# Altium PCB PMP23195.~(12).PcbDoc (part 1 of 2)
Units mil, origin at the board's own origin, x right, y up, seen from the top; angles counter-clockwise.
Board outline 3600 x 3375 mil, 4 copper layers (Top Layer, Signal Layer 1, Signal Layer 2, Bottom Layer), stack 39.6 mil thick; 101 components, 57 nets, 256 pads, 67 vias.
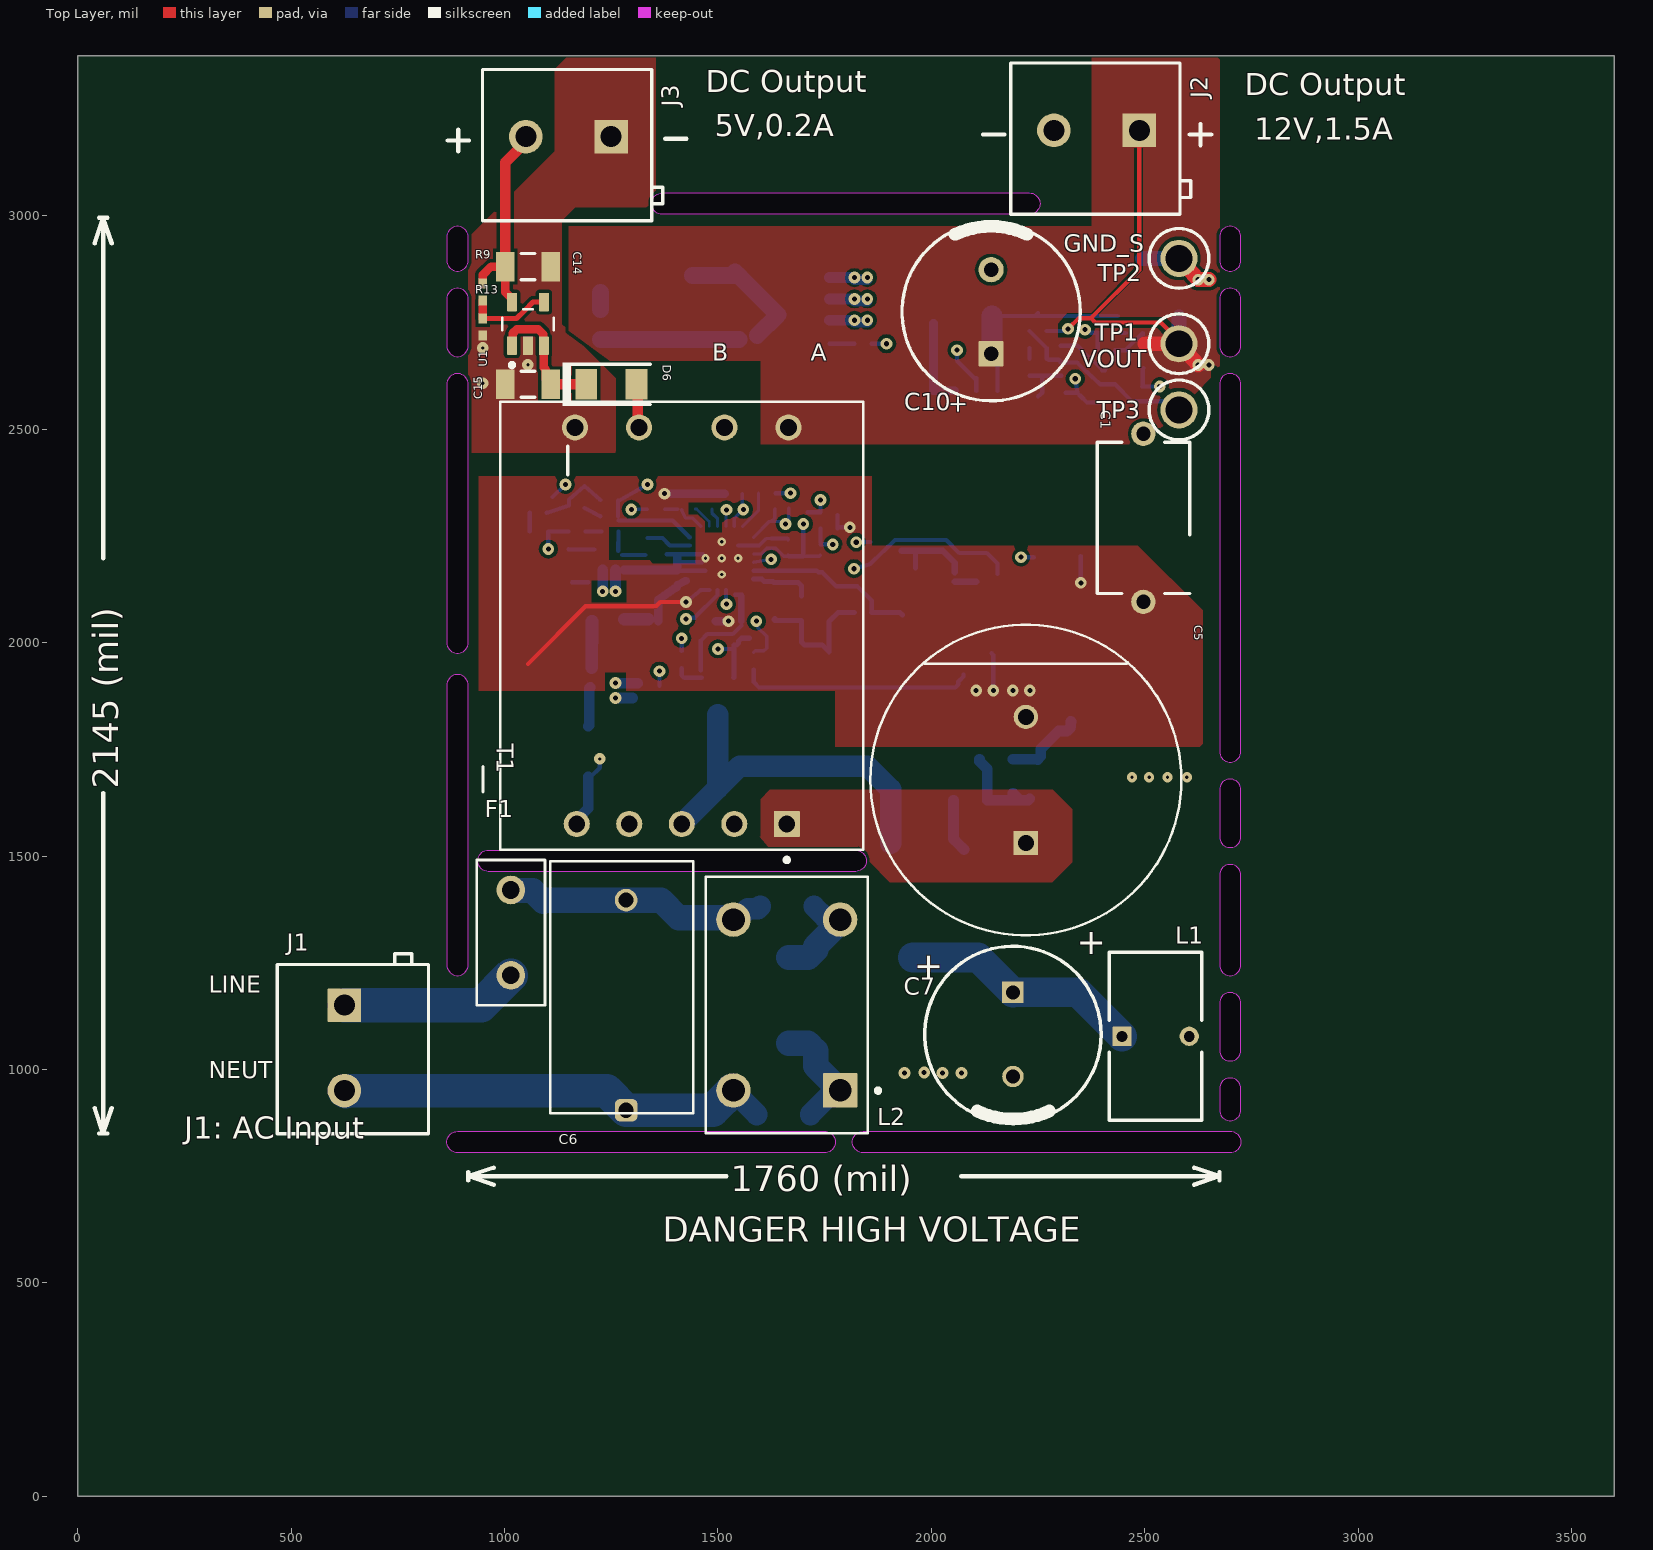
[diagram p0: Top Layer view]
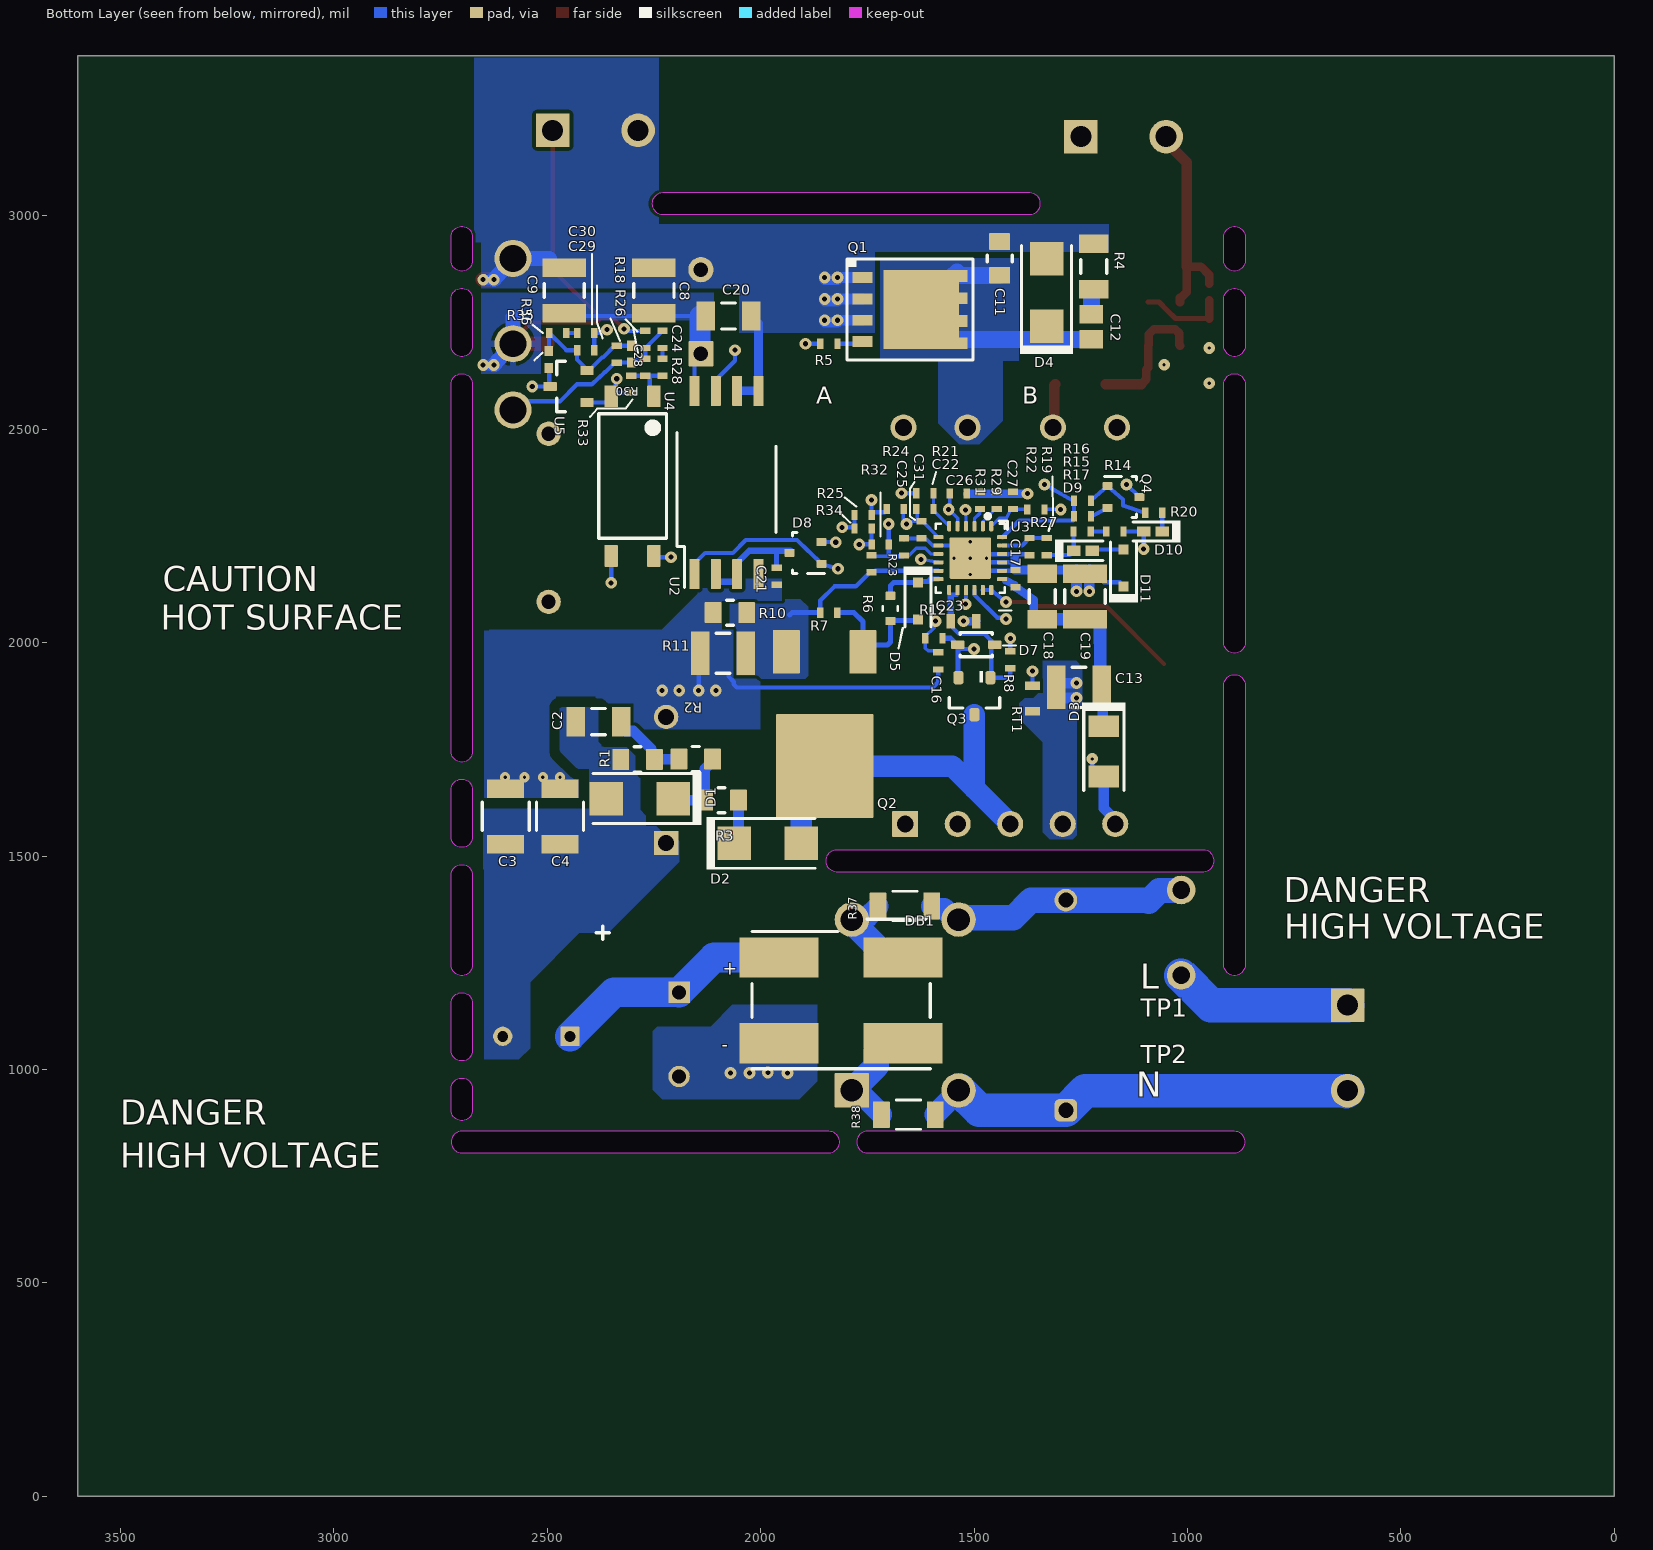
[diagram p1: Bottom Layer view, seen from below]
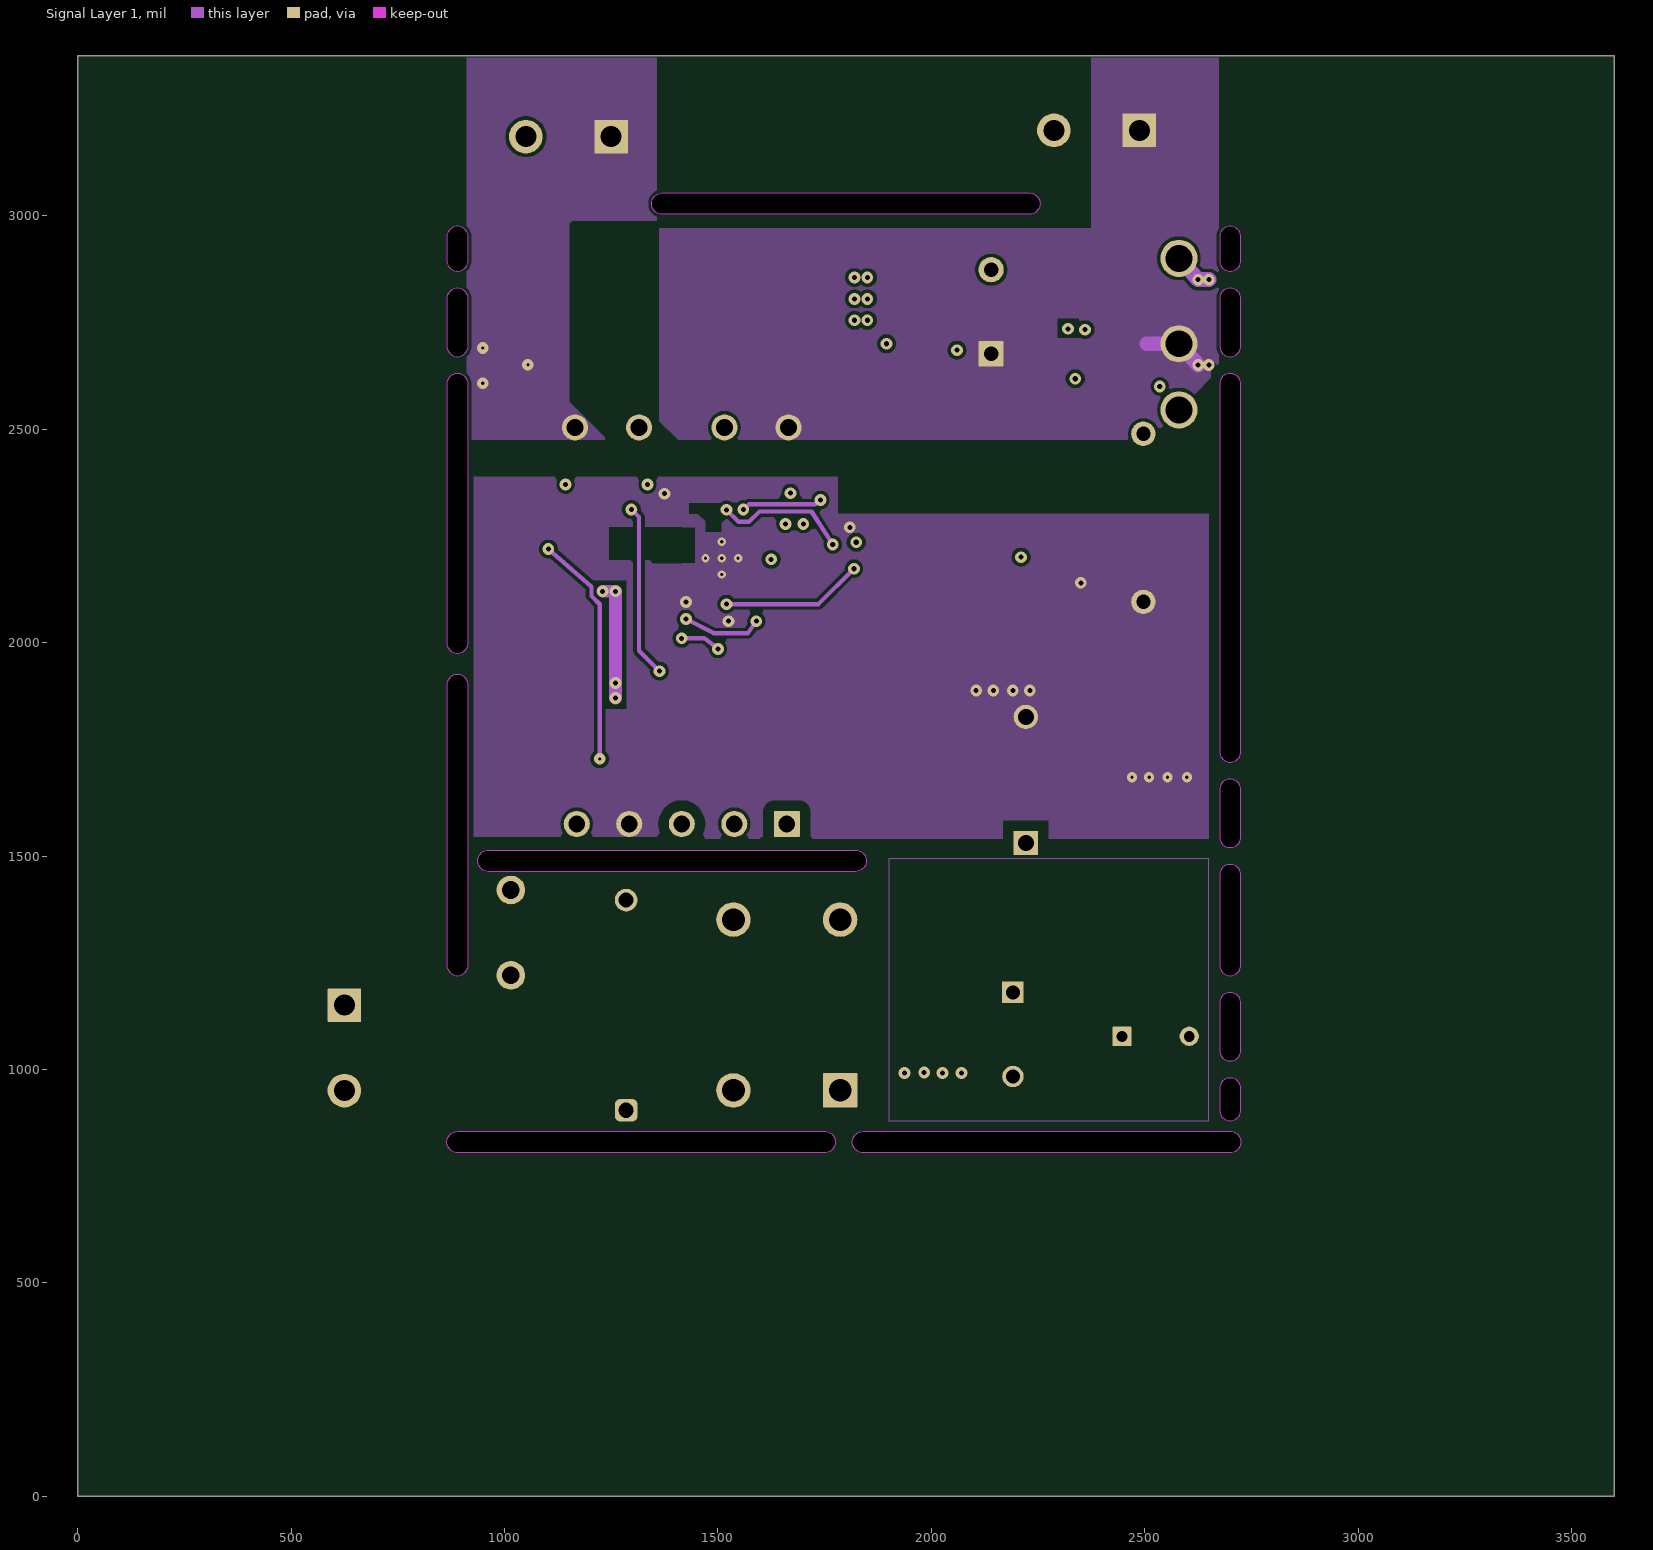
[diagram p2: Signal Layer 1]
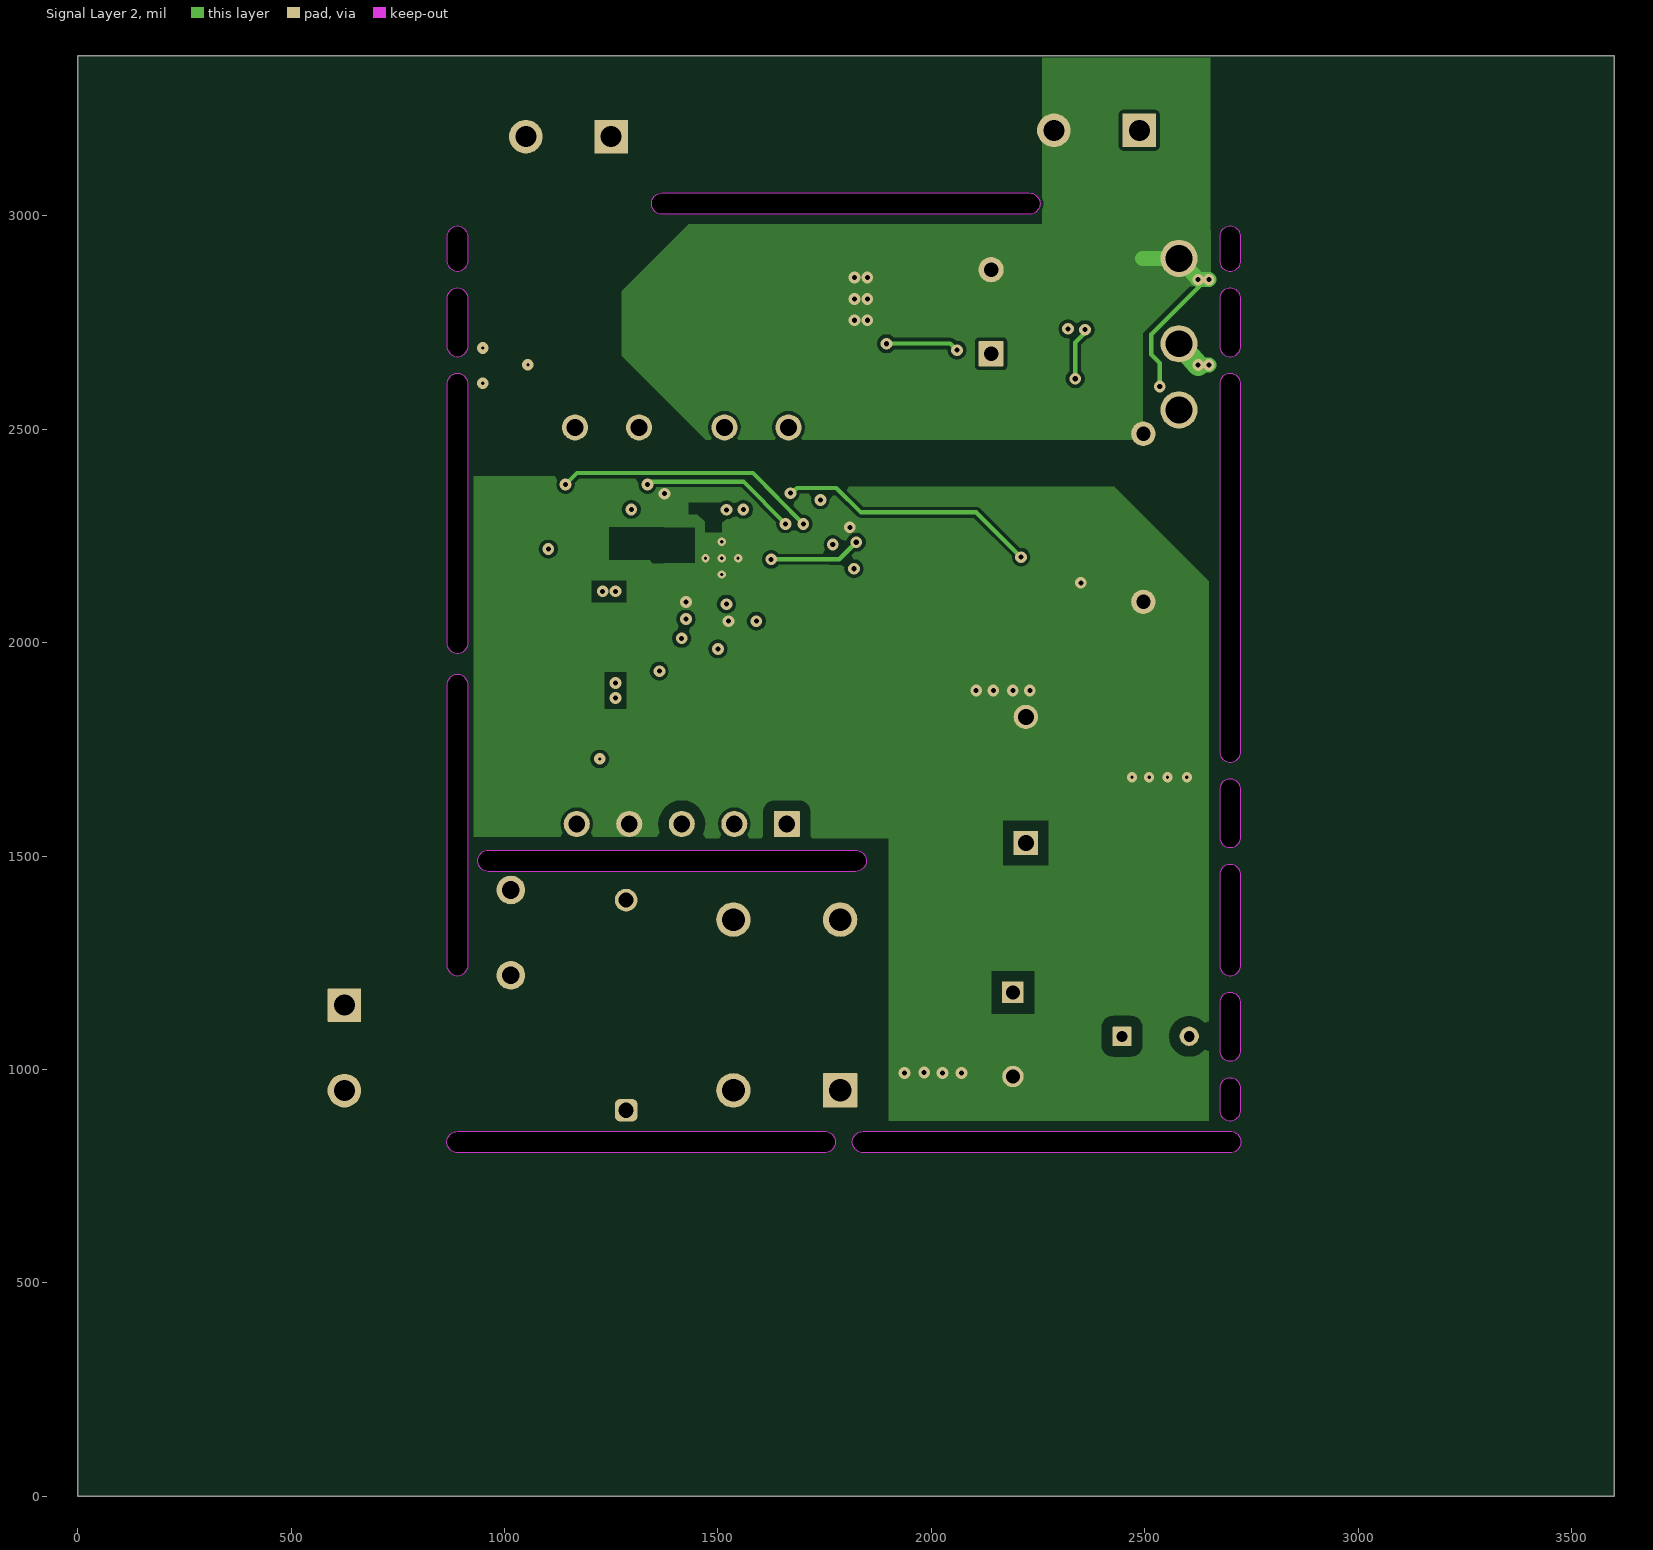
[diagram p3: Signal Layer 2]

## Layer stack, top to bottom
Top Solder: solder mask 0.4, Solder Resist, Dk 3.5
Top Layer: signal copper 1.4
Dielectric 1: prepreg 8, FR-4, Dk 4.2
Signal Layer 1: signal copper 1.4
Dielectric 2: core 18, FR-4, Dk 4.2
Signal Layer 2: signal copper 1.4
Dielectric 3: prepreg 8, FR-4, Dk 4.2
Bottom Layer: signal copper 1.4
Bottom Solder: solder mask 0.4, Solder Resist, Dk 3.5

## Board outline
0,0 3600,0 3600,3375 0,3375
cut-out: 962.45,1463.71 cw(c962.45,1488.72) 962.45,1513.74 1822.45,1513.74 cw(c1822.45,1488.72) 1847.47,1488.72 cw(c1822.45,1488.72) 1822.45,1463.71
cut-out: 1369.48,3003.15 cw(c1369.48,3028.16) 1369.48,3053.18 2229.48,3053.18 cw(c2229.48,3028.16) 2254.5,3028.16 cw(c2229.48,3028.16) 2229.48,3003.15
cut-out: 2674.99,2895 ccw(c2700,2895) 2725.01,2895 2725.01,2950 ccw(c2700,2950) 2674.99,2950
cut-out: 2674.99,2695 ccw(c2700,2695) 2725.01,2695 2725.01,2805 ccw(c2700,2805) 2674.99,2805
cut-out: 2674.99,1545 ccw(c2700,1545) 2725.01,1545 2725.01,1655 ccw(c2700,1655) 2674.99,1655
cut-out: 2674.99,1245 ccw(c2700,1245) 2725.01,1245 2725.01,1455 ccw(c2700,1455) 2674.99,1455
cut-out: 2674.99,1045 ccw(c2700,1045) 2725.01,1045 2725.01,1155 ccw(c2700,1155) 2674.99,1155
cut-out: 2674.99,905 ccw(c2700,905) 2725.01,905 2725.01,955 ccw(c2700,955) 2674.99,955
cut-out: 1840,804.99 cw(c1840,830) 1840,855.01 2700,855.01 cw(c2700,830) 2725.01,830 cw(c2700,830) 2700,804.99
cut-out: 890,804.99 cw(c890,830) 890,855.01 1750,855.01 cw(c1750,830) 1775.01,830 cw(c1750,830) 1750,804.99
cut-out: 864.98,1245 ccw(c890,1245) 915.02,1245 915.02,1900 ccw(c890,1900) 864.98,1900
cut-out: 864.98,2695 ccw(c890,2695) 915.02,2695 915.02,2805 ccw(c890,2805) 864.98,2805
cut-out: 864.98,2000 ccw(c890,2000) 915.02,2000 915.02,2605 ccw(c890,2605) 864.98,2605
cut-out: 864.98,2895 ccw(c890,2895) 915.02,2895 915.02,2950 ccw(c890,2950) 864.98,2950
cut-out: 2674.99,1745 ccw(c2700,1745) 2725.01,1745 2725.01,2605 ccw(c2700,2605) 2674.99,2605

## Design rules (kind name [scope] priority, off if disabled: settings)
AcuteAngle [All] p1: minimum=5.00000000000000E+0000 checktracksonly=FALSE
AssemblyTestPointUsage [All] p1: valid=2
BoardOutlineClearance BoardOutlineClearance_MountingHoles [OnCopper and InComponentClass('Mounting Holes')] p1: gap=15 ignorepadtopadclearanceinfootprint=FALSE
BoardOutlineClearance BoardOutlineClearance_Poly [OnCopper and InPoly] p2: gap=3.94 ignorepadtopadclearanceinfootprint=FALSE
BoardOutlineClearance [OnCopper and Not InComponentClass('Logo') and not InComponentClass('FiducialMark') and not InRegion(1000,500,4000,800)] p3: gap=4.53 ignorepadtopadclearanceinfootprint=FALSE
Clearance Clearance_HV [InNetClass('HV') vs not OnMultiLayer] p1: gap=25 ignorepadtopadclearanceinfootprint=TRUE // 1mm Clearance
Clearance Clearance_Keepouts [((IsTrack Or IsArc) And Not InPoly) And IsFree and IsKeepOut vs ((IsTrack Or IsArc) And Not InPoly) And IsFree and IsKeepOut] p2: gap=0 ignorepadtopadclearanceinfootprint=FALSE
Clearance Clearance_Poly [InPolygon] p3: gap=8 ignorepadtopadclearanceinfootprint=FALSE except(0: Arc-Hole Track-Hole SMDPad-Hole THPad-Hole Via-Hole Fill-Hole Poly-Hole Region-Hole Text-Hole)
Clearance [not InComponentClass('FiducialMark') vs not InComponentClass('FiducialMark')] p4: gap=6 ignorepadtopadclearanceinfootprint=FALSE
ComponentClearance ComponentClearance_MountingHoles_FiducialMarks [InComponentClass('Mounting Holes') vs InComponentClass('FiducialMark')] p1: gap=10 collisioncheckmode=3 verticalgap=10 showdistances=FALSE
ComponentClearance ComponentClearance_Shunt [InComponentClass('Header') vs InComponentClass('Shunt')] p2: gap=0 collisioncheckmode=3 verticalgap=0 showdistances=FALSE
ComponentClearance ComponentClearance_Logo [InComponentClass('Logo')] p3: gap=5 collisioncheckmode=3 verticalgap=0 showdistances=FALSE
ComponentClearance ComponentClearance_ScrewToNut [(HasFootprint('NY PMS 440 0025 PH')) vs (HasFootprint('Keystone_1902C'))] p4: gap=5 collisioncheckmode=3 verticalgap=10 showdistances=FALSE
ComponentClearance ComponentClearance_MountingHoles [InComponentClass('Mounting Holes')] p5: gap=10 collisioncheckmode=3 verticalgap=100000 showdistances=FALSE
ComponentClearance ComponentClearance_SmallPassives [HasFootprint('0201*') or HasFootprint('0402*') or HasFootprint('0508') or HasFootprint('0603*') or HasFootprint('0612') or HasFootprint('0805*') or HasFootprint('0815*') or HasFootprint('0830*') or HasFootprint('1206*') or HasFootprint('1210*') or HasFootprint('1808*') or HasFootprint('1812*') or HasFootprint('1825*') or HasFootprint('2010*') or HasFootprint('2220*') or HasFootprint('2225*') or HasFootprint('2512*') or HasFootprint('2728*') or HasFootprint('3518*') vs HasFootprint('0201*') or HasFootprint('0402*') or HasFootprint('0508') or HasFootprint('0603*') or HasFootprint('0612') or HasFootprint('0805*') or HasFootprint('0815*') or HasFootprint('0830*') or HasFootprint('1206*') or HasFootprint('1210*') or HasFootprint('1808*') or HasFootprint('1812*') or HasFootprint('1825*') or HasFootprint('2010*') or HasFootprint('2220*') or HasFootprint('2225*') or HasFootprint('2512*') or HasFootprint('2728*') or HasFootprint('3518*')] p6: gap=8 collisioncheckmode=3 verticalgap=10 showdistances=FALSE
ComponentClearance ComponentClearance_THtoSMT [IsThruComponent vs IsSMTComponent] p7: gap=10 collisioncheckmode=3 verticalgap=30 showdistances=FALSE
ComponentClearance ComponentClearance_THtoTH [IsThruComponent vs IsThruComponent] p8: gap=2 collisioncheckmode=3 verticalgap=30 showdistances=FALSE
ComponentClearance [All] p9: gap=8 collisioncheckmode=3 verticalgap=10 showdistances=FALSE
DiffPairsRouting [All] p1: maxlimit=100 minlimit=10 mostfreqgap=10 toplayer_minwidth=15 toplayer_maxwidth=15 toplayer_prefwidth=15 midlayer1_minwidth=15 midlayer1_maxwidth=15 midlayer1_prefwidth=15 midlayer2_minwidth=15 midlayer2_maxwidth=15 midlayer2_prefwidth=15 bottomlayer_minwidth=15 bottomlayer_maxwidth=15 bottomlayer_prefwidth=15 maxuncoupledlength=1000
FabricationTestPointUsage TestPointUsage [All] p1: valid=2 allowmultiple=FALSE
FabricationTestpoint Testpoint [All] p1: side=3 testpointundercomponent=TRUE minsize=40 maxsize=100 preferedsize=60 minholesize=0 maxholesize=40 preferedholesize=32 testpointgrid=1 allowsidetop=TRUE allowsidebottom=TRUE usegrid=TRUE gridtolerance=0.01
FanoutControl Fanout_LCC [IsLCC] p1: bgadir=Out bgaviamode=Centered fanoutstyle=Auto fanoutdirection=Alternating viagrid=1 // Fanout_LCC (Default Rule)
FanoutControl Fanout_BGA [IsBGA] p2: bgadir=Out bgaviamode=Centered fanoutstyle=Auto fanoutdirection=Alternating viagrid=1 // Fanout_BGA (Default Rule)
FanoutControl Fanout_Default [All] p4: bgadir=Out bgaviamode=Centered fanoutstyle=Auto fanoutdirection=Alternating viagrid=1 // Fanout_Default (Default Rule)
FanoutControl Fanout_Small [(CompPinCount < 5)] p5: bgadir=Out bgaviamode=Centered fanoutstyle=Auto fanoutdirection=OutThenIn viagrid=1 // Fanout_Small (Default Rule)
HoleSize [All] p1: absolutevalues=TRUE maxlimit=251 minlimit=7.87 maxpercent=80.000 minpercent=20.000
HoleToHoleClearance [All] p1: gap=7.87 allowstackedmicrovias=TRUE
MinimumAnnularRing MinimumAnnularRing_ThermalPadVias [IsVia and InAnyComponent] p1: minimumring=5.91
MinimumAnnularRing [All] p2: minimumring=5
MinimumSolderMaskSliver MinimumSolderMaskSliver_Logo [InComponentClass('Logo') vs InComponentClass('Logo')] p1: minsoldermaskwidth=0
MinimumSolderMaskSliver [All] p2: minsoldermaskwidth=1
PlaneConnect [All] p1: planeconnectstyle=Direct reliefexpansion=10 reliefentries=4 reliefconductorwidth=10 reliefairgap=10
PolygonConnect [All] p1: connectstyle=Direct reliefconductorwidth=15.75 reliefentries=4 polygonreliefangle="90 Angle" airgapwidth=7.87
RoutingVias ThermalPadVias [IsVia and InAnyComponent] p1: holewidth=7.87 width=19.68 viastyle="Through Hole" minholewidth=7.87 minwidth=19.68 maxholewidth=12.99 maxwidth=23.62
RoutingVias [All] p2: holewidth=16 width=34 viastyle="Through Hole" minholewidth=7.87 minwidth=26 maxholewidth=40 maxwidth=65
SilkToBoardRegionClearance [Not ((IsComment or IsDesignator) And (Hide <> 'False')) and not InRegion(1000,500,4000,800)] p1:
SilkToSilkClearance SilkToSilkClearance_Pb-FreeLogo [(HasFootprint('Pb-Free_Overlay_Medium') OR HasFootprint('Pb-Free_Overlay_Small')) vs (HasFootprint('Pb-Free_Overlay_Medium') OR HasFootprint('Pb-Free_Overlay_Small'))] p1: silktosilkclearance=0
SilkToSilkClearance [All] p2: silktosilkclearance=0.5
SilkToSolderMaskClearance SilkToComponentPadClearance [IsPad and InAnycomponent] p1: minsilkscreentomaskgap=0.5 clearancetoexposedcopper=TRUE
SilkToSolderMaskClearance "Silk to Solder Mask Opening" [All] p2: minsilkscreentomaskgap=0 clearancetoexposedcopper=FALSE
SolderMaskExpansion [All] p1: expansion=1.97 istentingtop=FALSE
Width [All] p1: maxlimit=100 minlimit=5 preferedwidth=10 checkconnectedcopper=TRUE
14 further rules are at their usual default settings.

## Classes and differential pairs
net class Secondary: GND_S
net class Primary: GND_P
net class HV: NetC7_1 Vbulk Vswn

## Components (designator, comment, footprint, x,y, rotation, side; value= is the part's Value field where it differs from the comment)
C1 "C921U222MVVDBA7317" C900_9x13 2496.65,2292.24 r270 top value=2200pF
C2 "GRM31BR72J102KW01L" 1206L 2380,1815 r180 bottom value=1000pF
C3 "C1210C104KBRAC7800" 1210_280 2597.16,1592.95 r270 bottom value=0.1uF
C4 "C1210C104KBRAC7800" 1210_280 2470,1592.95 r270 bottom value=0.1uF
C5 "450BXW22MEFR18X16" FP-450BXW22MEFR18X16_RADIAL-MFG 2221.3,1678.11 r270 top
C6 "890324024003" WCAP-FTX2_1500x850 1285,1150.47 r90 top value=0.33uF
C7 "UVC2G150MPD" UVC_1000x1600 2191,1082 r270 top value=15uF
C8 "GRM32ER71E226KE15L" 1210_270L 2250,2825 r90 bottom value=22uF
C9 "GRM32ER71E226KE15L" 1210_270L 2460,2825 r90 bottom value=22uF
C10 "APSG200ELL681MJB5S" PSG_1000x1150 2140,2775 r90 top value=680uF
C11 "GRM21AR72E152KW01D" 0805_HV1 1440,2900 r90 bottom value=1500pF
C12 "GRM21AR72E102KW01D" 0805L 1225,2740 r270 bottom value=1000pF
C13 "GMK325BJ226MM-P" 1210L 1254.15,1895 r180 bottom value=22uF
C14 "C3216X5R1H106K160AB" 1206_180L 1055,2880.83 r0 top value=10uF
C15 "C3216X5R1H106K160AB" 1206_180L 1055,2605 r180 top value=10uF
C16 "GCM1555C1H220JA16D" 0402S 1583.77,1957 r90 bottom value=22pF
C17 "GRM155R71H104ME14D" 0402S 1403,2150 r90 bottom value=0.1uF
C18 "C3216X5R1H106K160AB" 1206_180L 1340,2108 r90 bottom value=10uF
C19 "GMK325BJ226MM-P" 1210L 1240,2108 r270 bottom value=22uF
C20 "C1206C106J3RACAUTO" 1206_180L 2075,2765 r180 bottom value=10uF
C21 "GRM155R71H104ME14D" 0402S 1962.37,2155 r270 bottom value=0.1uF
C22 "GRM155R71H331KA01D" 0402S 1615,2313 r180 bottom value=330pF
C23 "CGA3E1X7R1V105K080AC" 0603S 1525,2050 r180 bottom value=1uF
C24 "GRM155R71H153KA12D" 0402S 2230,2710 r90 bottom value=0.015uF
C25 "GRM1555C1H101JA01D" 0402S 1664,2224 r90 bottom value=100pF
C26 "GRM155R71H331KA01D" 0402S 1537.14,2349.3 r180 bottom value=330pF
C27 "GRM1555C1H101JA01D" 0402S 1409,2333 r270 bottom value=100pF
C28 "GCM1555C1H220JA16D" 0402S 2337.06,2675.67 r270 bottom value=22pF
C29 "GCM1555C1H220JA16D" 0402S 2410,2685 r0 bottom value=22pF
C30 "GRM155R71H103KA88D" 0402S 2410,2725 r180 bottom value=0.01uF
C31 "GRM155R71C224KA12D" 0402S 1623,2264 r270 bottom value=0.22uF
D1 "SMAJ150A" SMA 2283,1634.37 r0 bottom value=150V
D2 "MRA4007T3G" SMA 1983.18,1529.83 r180 bottom value=1000V
D3 "CSFMT104-HF" SOD-123H 1196.18,1745 r270 bottom value=200V
D4 "SMAJ120A" SMA 1330,2820 r90 bottom value=120V
D5 "BAS316,115" SOD-323 1631,2097 r270 bottom value=100V
D6 "CSFMT104-HF" SOD-123H 1250.55,2605 r0 top value=200V
D7 "CDSOD323-T18C" FP-CDSOD323-T18C_SOD323-MFG 1495,1995 r180 bottom value=18V
D8 "BAS40W-05-7-F" SOT-323 1895,2210 r0 bottom value=40V
D9 "1N4148X-TP" SOD-523 1245,2215 r180 bottom value=75V
D10 "BZT585B39T-7" SOD-523 1081,2260 r0 bottom value=39V
D11 "SZMM3Z27VST1G" SOD-323 1150,2175 r90 bottom value=27V
DB1 "Z4DGP406L-HF" Z4-D 1811.67,1161.85 r180 bottom value=600V
F1 "39213150000" FUSE_392 1015,1320.47 r270 top
J1 "ED120/2DS" On-Shore_ED120_2DS 625,1050.47 r270 top
J2 "ED120/2DS" On-Shore_ED120_2DS 2387,3200 r180 top
J3 "ED120/2DS" On-Shore_ED120_2DS 1150,3185 r180 top
L1 "7447052" FP-7447052_PTH_D10MM0-MFG 2525.33,1077.65 r90 top
L2 "RLTI-1387" FP-RLTI-1387_PTH_CMC_0IN38_0IN60-MFG 1661.31,1151.02 r90 top
Q1 "BSC093N15NS5ATMA1" PG-TDSON-8 1650,2780 r180 bottom value=150V
Q2 "IPD80R600P7ATMA1" DPAK 1850,1844.51 r270 bottom value=800V
Q3 "CPC3982TTR" SOT-23L 1499.2,1874.45 r270 bottom value=800V
Q4 "MMST3906-7-F" SOT-323 1150.02,2341 r180 bottom value="40 V"
R1 "CRCW0805470KJNEA" 0805_HV1 2288.18,1726.26 r0 bottom value=470k
R2 "CRCW080515R0JNEA" 0805_HV1 2152,1726.98 r0 bottom value=15
R3 "CRCW080515R0JNEA" 0805_HV1 2091.29,1630.74 r0 bottom value=15
R4 "CRCW120610R0JNEA" 1206L 1220,2880.81 r270 bottom value=10
R5 "CRCW040210R0JNED" 0402S 1840,2700 r180 bottom value=10
R6 "RK73H1JTTD1000F" FP-RK73H1JTTD1000F_0603-MFG 1696,2080 r270 bottom
R7 "CRCW040210K0FKED" 0402S 1840.31,2070 r180 bottom value=10.0k
R8 "CRCW04021M00JNED" 0402S 1415,1960 r270 bottom value=1.0Meg
R9 "RC0402FR-07100KL" 0402L 949,2821.17 r90 top value=100k
R10 "ERJ-6RQFR68V" 0805_HV1 2072.02,2070 r0 bottom value=0.68
R11 "MCR25JZHFLR220" 1210L 2087.98,1975 r180 bottom value=0.22
R12 "CRCW0402511RFKED" 0402S 1593.9,2010 r180 bottom value=511
R13 "CRCW040233K2FKED" 0402L 949,2739.3 r90 top value=33.2k
R14 "CRCW04022K10FKED" 0402S 1170,2260 r0 bottom value=2.10k
R15 "CRCW040227K4FKED" 0402S 1246,2296 r180 bottom value=27.4k
R16 "CRCW04021K00FKED" 0402S 1246,2332 r180 bottom value=1.00k
R17 "CRCW04022K10FKED" 0402S 1247,2260 r0 bottom value=2.10k
R18 "RC0402JR-070RL" 0402S 2270,2710 r270 bottom value=0
R19 "CRCW040215K4FKED" 0402S 1330,2225 r90 bottom value=15.4k
R20 "CRCW040210K0FKED" 0402S 1079,2304 r180 bottom value=10.0k
R21 "CRCW040220K0FKED" 0402S 1615,2350 r0 bottom value=20.0k
R22 "CRCW04026K98FKED" 0402S 1370,2225 r90 bottom value=6.98k
R23 "CRCW04021K00FKED" 0402S 1740,2184.41 r270 bottom value=1.00k
R24 "CRCW0402191KFKED" 0402S 1685,2313 r0 bottom value=191k
R25 "CRCW040239K2FKED" 0402S 1760,2299 r0 bottom value=39.2k
R26 "CRCW040215K0FKED" 0402S 2270,2645 r90 bottom value=15.0k
R27 "CRCW04023K32FKED" 0402S 1355,2312 r0 bottom value=3.32k
R28 "CRCW0402511RFKED" 0402S 2230,2645 r90 bottom value=511
R29 "CRCW0402169KFKED" 0402S 1446.59,2332.88 r270 bottom value=169k
R30 "CRCW0402154KFKED" 0402L 2303.15,2675.67 r270 bottom value=154k
R31 "CRCW040293K1FKED" 0402S 1485.96,2332.88 r270 bottom value=93.1k
R32 "CRCW04021M00JNED" 0402S 1720,2230 r180 bottom value=1.0Meg
R33 "CRCW04025K62FKED" 0402S 2303.15,2605 r90 bottom value=5.62k
R34 "CRCW04020000Z0EDHP" 0402S 1760,2267 r180 bottom value=0
R35 "CRCW040210K0FKED" 0402S 2475,2725 r0 bottom value=10.0k
R36 "CRCW040240K2FKED" 0402L 2496.65,2662.99 r90 bottom value=40.2k
R37 "RMCF1206ZT0R00" FP-RMCF1206ZT0R00_1206-MFG 1662.21,1383 r0 bottom value=0
R38 "RMCF1206ZT0R00" FP-RMCF1206ZT0R00_1206-MFG 1654,894 r0 bottom value=0
RT1 "NCP18WB473J03RB" 0603S 1362.93,1868.9 r270 bottom value=47k
T1 "RLTI-1446" FP-RLTI-1446_PTH9_1IN05_0IN85-MFG 1415.31,2039.5 r90 top
TP1 "VOUT" Keystone5012 2580,2700 r90 top
TP2 "GND_S" Keystone5011 2580,2900 r90 top
TP3 "VOUT_A" Keystone5012 2580,2545 r90 top
U1 "TPS7A2401DBVR" DBV0005A-MFG 1055,2746.5 r90 top
U2 "UCC5304DWV" DWV0008A 2080,2375 r90 bottom locked
U3 "UCC28781QRTWRQ1" RTW0024B-MFG 1508.96,2197.72 r270 bottom
U4 "TLP383(GR-TPL,E" FP-TLP383(GR-TPL,E_SO6-4-MFG 2300,2390 r270 bottom locked
U5 "ATL431AIDBZR" DBZ0003A_L 2450,2600 r0 bottom

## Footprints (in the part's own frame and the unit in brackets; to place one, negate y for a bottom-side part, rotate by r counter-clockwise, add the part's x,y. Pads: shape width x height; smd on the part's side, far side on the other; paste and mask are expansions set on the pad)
0402L [mm] "0402 from SM-752 data"
  rect 0.6x0.5 smd: 1(-0.5,0) 2(0.5,0)
  body extent -0.55,-0.3 0.55,0.3, height 0.6
0402S [mil] "Based on C0402S footprint from PADS legacy"
  rect 15x24 smd: 1(-20,0) 2(20,0)
  body extent -22,-12 22,12, height 24
0603S [mil]
  rect 20x35 smd: 1(-30,0) 2(30,0)
  body extent -34,-19 34,19, height 39
0805_HV1 [mm] "Custom footprint based on analyzing multiple manufacturer recommendations"
  rrect10% 1x1.25 smd: 1(-1,0) 2(1,0)
  silkscreen extent -0.2,-0.75 0.2,0.75, body extent -1.1,-0.72 1.1,0.73, height 1.45
0805L [mm] "0805 from SM-752 data"
  rect 1.1x1.4 smd: 1(-0.75,0) 2(0.75,0)
  body extent -1.1,-0.72 1.1,0.72, height 1.45
1206_180L [mm] "1206_180"
  rect 1.1x1.75 smd: 1(-1.35,0) 2(1.35,0)
  silkscreen extent -0.4,-0.77 0.4,0.77, body extent -1.75,-0.95 1.75,0.95, height 1.8
1206L [mm] "1206 from SM-752 data"
  rect 1.1x1.75 smd: 1(-1.35,0) 2(1.35,0)
  silkscreen extent -0.4,-0.77 0.4,0.77, body extent -1.7,-0.9 1.7,0.9, height 1.35
1210_270L [mm] "1210"
  rect 1.1x2.6 smd: 1(-1.35,0) 2(1.35,0)
  silkscreen extent -0.4,-1.2 0.4,1.2, body extent -1.7,-1.35 1.7,1.35, height 2.7
1210_280 [mm] "SMD, 2-Leads, Body 3.6x2.8mm, Height 2.8mm"
  rect 1.1x2.2 smd: 1(-1.65,0) 2(1.65,0)
  silkscreen extent -0.84,-1.4 0.84,1.4, body extent -1.8,-1.4 1.8,1.4, height 2.8
1210L [mm] "1210 from SM-752 data"
  rect 1.1x2.6 smd: 1(-1.35,0) 2(1.35,0)
  silkscreen extent -0.4,-1.2 0.4,1.2, body extent -1.7,-1.35 1.7,1.35, height 1.35
C900_9x13 [mm] "Kemet"
  round 1.45 hole 0.85: 1(-5,0) 2(5,0)
  silkscreen extent -4.5,-2.75 4.5,2.76, body extent -4.49,-2.75 4.49,2.75, height 12.96
DBV0005A-MFG [mm]
  rrect17% 1.1x0.6 smd paste+0 mask+0: 1(-1.3,0.95) 2(-1.3,0) 3(-1.3,-0.95) 4(1.3,-0.95) 5(1.3,0.95)
  silkscreen extent -2.57,-1.53 0.87,1.53, body extent -1.95,-1.78 1.95,1.78, height 0.25
DBZ0003A_L [mm] "SOT23, 3-Leads, Body 2.9x1.3mm, Pitch 0.95mm, Lead Span 2.4mm, IPC High Density"
  rrect18% 0.8x0.55 smd: 1(-1.1,0.95) 2(-1.1,-0.95) 3(1.1,0)
  silkscreen extent 0.2,-1.5 0.7,1.5, body extent -1.26,-1.46 1.26,1.46, height 0.98
DPAK [mm] "D-PAK, 3-Pads, Body 6.22x6.73mm (max), TO-252AA using nominal STEP model"
  rrect6% 2.6x1.6 smd: 1(-3.4,2.28) 3(-3.4,-2.28)
  rrect2% 6.2x5.8 smd paste-3: 2(3.4,0)
  body extent -3.86,-3.29 5.84,3.29, height 2.48
DWV0008A [mm] "SOIC, 8-Leads, Body 5.95x7.6mm (max), Pitch 1.27mm"
  rrect17% 1.8x0.6 smd: 1(-5.45,1.905) 2(-5.45,0.635) 3(-5.45,-0.635) 4(-5.45,-1.905) 5(5.45,-1.905) 6(5.45,-0.635) 7(5.45,0.635) 8(5.45,1.905)
  silkscreen extent -6.25,-2.95 2.98,2.95, body extent -5.77,-2.92 5.77,2.93, height 2.67
FP-450BXW22MEFR18X16_RADIAL-MFG [mm]
  round 1.45 hole 0.95 paste-1000 mask+0: 1(-3.75,0)
  rect 1.45x1.45 hole 0.95 paste-1000 mask+0: 2(3.75,0)
  silkscreen extent -9.25,-9.25 9.25,9.25, body extent -9.35,-9.35 9.35,9.35, height 0.25
FP-7447052_PTH_D10MM0-MFG [mm]
  rrect9% 1.15x1.15 hole 0.65 paste-1000: 1(0,2)
  round 1.15 hole 0.65 paste-1000: 2(0,-2)
  silkscreen extent -5,-2.75 5,2.75, body extent -5.1,-2.85 5.1,2.85, height 0.25
FP-CDSOD323-T18C_SOD323-MFG [mm]
  rrect20% 0.8x0.5 smd paste+0 mask+0: 1(-1.1,0) 2(1.1,0)
  silkscreen extent -0.95,-0.72 0.95,0.72, body extent -1.27,-0.65 1.27,0.65, height 1.14
FP-RK73H1JTTD1000F_0603-MFG [mm]
  rrect20% 0.5x0.6 smd paste+0 mask+0: 1(-0.75,0) 2(0.75,0)
  silkscreen extent -0.13,-0.45 0.13,0.45, body extent -0.8,-0.4 0.8,0.4, height 0.55
FP-RLTI-1387_PTH_CMC_0IN38_0IN60-MFG [mm]
  rrect5% 2.05x2.05 hole 1.35 paste-1000: 1(-5.08,-3.175)
  round 2.05 hole 1.35 paste-1000: 2(-5.08,3.175) 3(5.08,3.175) 4(5.08,-3.175)
  silkscreen extent -7.62,-5.55 7.62,4.83, body extent -7.72,-4.93 7.72,4.93, height 0.25
FP-RLTI-1446_PTH9_1IN05_0IN85-MFG [mm]
  rrect6% 1.55x1.55 hole 1 paste-1000 mask+0: 1(-11.798,-6.248)
  round 1.55 hole 1 paste-1000 mask+0: 2(-11.798,-3.124) 3(-11.798,0) 4(-11.798,3.124) 5(-11.798,6.248) 6(11.798,6.35) 7(11.798,2.54) 8(11.798,-2.54) 9(11.798,-6.35)
  silkscreen extent -14.06,-10.8 13.33,10.8, body extent -13.43,-10.89 13.43,10.89, height 0.25
FP-RMCF1206ZT0R00_1206-MFG [mm]
  rrect10% 1x1.6 smd paste+0 mask+0: 1(-1.6,0) 2(1.6,0)
  silkscreen extent -0.72,-0.87 0.72,0.87, body extent -1.6,-0.8 1.6,0.8, height 0.7
FP-TLP383(GR-TPL,E_SO6-4-MFG [mm]
  rrect13% 1.3x0.8 smd paste+0 mask+0: 1(-4.75,1.27) 3(-4.75,-1.27) 4(4.75,-1.27) 6(4.75,1.27)
  silkscreen extent -3.7,-2.02 3.7,2.02, body extent -5.01,-1.92 5.01,1.92, height 2.3
FUSE_392 [mm] "LITTELFUSE"
  round 1.7 hole 1.05: 1(-2.54,0) 2(2.54,0)
  silkscreen extent -4.32,-2.03 4.32,2.03, body extent -4.25,-2 4.25,2, height 8
Keystone5011 [mil] "Keystone Multipurpose loops"
  round 87 hole 63: 1(0,0)
  silkscreen extent -70,-70 70,70, body extent -63,-63 63,62, height 319
Keystone5012 [mil] "Keystone Multipurpose loops"
  round 87 hole 63: 1(0,0)
  silkscreen extent -70,-70 70,70, body extent -63,-63 63,62, height 319
On-Shore_ED120_2DS [mm] "ONSHORE"
  rrect5% 2x2 hole 1.25: 1(-2.54,0)
  round 2 hole 1.25: 2(2.54,0)
  silkscreen extent -5.6,-4 5.12,5, body extent -5.78,-4 5.08,5, height 13
PG-TDSON-8 [mm] "Infineon recommended land pattern"
  rect 1.2x0.65 smd: 1(-2.825,1.905) 2(-2.825,0.635) 3(-2.825,-0.635) 4(-2.825,-1.905)
  rect 0.5x0.7 smd: 5(3.175,-2) 6(3.175,-0.675) 7(3.175,0.675) 8(3.175,2)
  rect 4.5x4.7 smd paste-2.25: 9(0.675,0)
  silkscreen extent -3.74,-3 3.74,3, body extent -3.18,-2.89 3.18,2.9, height 1.1
PSG_1000x1150 [mm] "United Chemi-Con"
  rrect7% 1.5x1.5 hole 0.85: 1(-2.5,0)
  round 1.5 hole 0.85: 2(2.5,0)
  silkscreen extent -5.3,-5.3 5.3,5.3, body extent -5.25,-5.25 5.25,5.25, height 13.01
RTW0024B-MFG [mm]
  rrect42% 0.6x0.24 smd paste+0 mask+0: 1(-1.9,1.25) 2(-1.9,0.75) 3(-1.9,0.25) 4(-1.9,-0.25) 5(-1.9,-0.75) 6(-1.9,-1.25) 13(1.9,-1.25) 14(1.9,-0.75) 15(1.9,-0.25) 16(1.9,0.25) 17(1.9,0.75) 18(1.9,1.25)
  rrect42% 0.24x0.6 smd paste+0 mask+0: 7(-1.25,-1.9) 8(-0.75,-1.9) 9(-0.25,-1.9) 10(0.25,-1.9) 11(0.75,-1.9) 12(1.25,-1.9) 19(1.25,1.9) 20(0.75,1.9) 21(0.25,1.9) 22(-0.25,1.9) 23(-0.75,1.9) 24(-1.25,1.9)
  rrect4% 2.45x2.45 smd paste-1000 mask+0: 25(0,0)
  silkscreen extent -2.62,-2.05 2.05,2.05, body extent -2,-2 2,2, height 0.8
SMA [mm] "Molded Diode, 2-Leads, Body 4.3x2.6mm, IPC Medium Density, based on OnSemi component dimensions and land pattern"
  rect 2x2 smd: 1(-2,0) 2(2,0)
  silkscreen extent -3.66,-1.57 2.79,1.57, body extent -2.6,-1.3 2.6,1.3, height 2.42
SOD-123H [mm] "SMT, 2-Leads, Body 3.5x1.6mm"
  rect 1.3x1.8 smd: 1(-1.5,0) 2(1.5,0)
  silkscreen extent -2.9,-1.3 2.3,1.3, body extent -1.9,-0.9 1.9,0.9, height 1
SOD-323 [mm] "NXP recommended land pattern"
  rect 0.6x0.6 smd paste-0.05: 1(-1.1,0) 2(1.1,0)
  silkscreen extent -2.06,-0.86 1.53,0.86, body extent -1.3,-0.67 1.3,0.68, height 1.1
SOD-523 [mm] "NXP Semiconductor recommended land pattern, nominal STEP model"
  rect 0.8x0.6 smd paste-0.05: 1(-0.55,0) 2(0.55,0)
  silkscreen extent -1.65,-0.66 1.2,0.66, body extent -0.8,-0.4 0.8,0.4, height 0.72
SOT-23L [mm] "SOT23, 3-Leads, Body 2.9x1.3mm, Pitch 0.95mm, Lead Span 2.5mm, IPC High Density"
  rrect50% 0.8x0.6 smd: 1(-1.1,0.95) 2(-1.1,-0.95) 3(1.1,0)
  silkscreen extent -1.5,-1.5 0.7,1.5, body extent -1.16,-1.45 1.21,1.45, height 1
SOT-323 [mm] "Diodes Inc recommended land pattern.  2016-02-24"
  rrect21% 0.6x0.47 smd: 1(-0.95,0.65) 2(-0.95,-0.65) 3(0.95,0)
  silkscreen extent -1.14,-1.22 0.77,1.22, body extent -1.13,-1.13 1.12,1.12, height 1.13
UVC_1000x1600 [mm] "TH, 2-Leads, Dia 10mm, Lead Spacing 5mm"
  rect 1.275x1.275 hole 0.85: 1(-2.5,0)
  round 1.275 hole 0.85: 2(2.5,0)
  silkscreen extent -5.25,-5.25 5.25,5.25, body extent -5.25,-5.25 5.26,5.25, height 18.01
WCAP-FTX2_1500x850 [mm] "TH, 2-Leads, Body 15x8.5mm"
  rrect50% 1.35x1.35 hole 0.9: 1(-6.25,0)
  round 1.35 hole 0.9: 2(6.25,0)
  body extent -7.5,-4.25 7.5,4.25, height 14
Z4-D [mm] "SMD, 4-Leads, Body 8.1x10.5mm"
  rect 4.7x2.4 smd: 1(-3.7,2.55) 2(3.7,2.55) 3(3.7,-2.55) 4(-3.7,-2.55)
  silkscreen extent -5.3,-4.07 5.3,4.1, body extent -5.3,-4.1 5.3,4.1, height 1.56

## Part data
C1: library part CMP-0078358-1, "CAP, CERM, 2200 pF, X1 400 VAC/Y1 400 VAC, +/- 20%, Y5V, D9xL13mm", Cap_Case=9x13mm, Manufacturer=Kemet, Supplier Part Number 1=399-9487-1-ND, TempCo=Y5V, Tolerance_%=20%, ValueDisplayed=2200pF
C2: library part CMP-0008909-2, "CAP, CERM, 1000 pF, 630 V, +/- 10%, X7R, 1206", Cap_Case=1206, Manufacturer=MuRata, Supplier Part Number 1=490-3506-1-ND, TempCo=X7R, Tolerance_%=10%, Value1=Unknown, Value2=630V, ValueDisplayed=1000pF
C3 C4: library part CMP-0009076-1, "CAP, CERM, 0.1 uF, 630 V, +/- 10%, X7R, 1210", Cap_Case=1210, Manufacturer=Kemet, Supplier Part Number 1=399-13490-1-ND, TempCo=X7R, Tolerance_%=10%, Value1=Unknown, Value2=630V, ValueDisplayed=0.1uF
C5: library part CMP-0088960-1, "Cap Aluminum Lytic 22uF 450V 20% (18 X 16mm) Radial 7.5mm 340mA 10000h 105C", Digikey Part Number=1189-3181-ND, Leakage Current=298uA, Manufacturer=Rubycon, Mouser Part Number=232-450BXW22MEFR18X1, Operating Temperature Range="-40°C to +105°C", Tolerance_%=20%, ValueDisplayed=22uF
C6: library part CMP-0084596-1, "CAP, Film, 0.33 µF, X2 275 VAC, +/- 10%, TH", Cap_Case=15x8.5mm, Manufacturer="Wurth Elektronik", Tolerance_%=10%, ValueDisplayed=0.33µF
C7: library part CMP-0860955-2, "CAP, AL, 15 µF, 400 V, +/- 20%, AEC-Q200 Grade 2, TH", Cap_Case=10x16, Manufacturer=Nichicon, Tolerance_%=20%, Value2=400V, ValueDisplayed=15µF
C8 C9: library part CMP-0009224-2, "CAP, CERM, 22 uF, 25 V, +/- 10%, X7R, 1210", Cap_Case=1210, Manufacturer=MuRata, Supplier Part Number 1=490-5313-1-ND, TempCo=X7R, Tolerance_%=10%, Value1=Unknown, Value2=25V, ValueDisplayed=22uF
C10: library part CMP-0012176-3, "CAP, Aluminum Polymer, 680 uF, 20 V, +/- 20%, 0.012 ohm, TH", Cap_Case=10x11.5, Manufacturer=Chemi-Con, Supplier Part Number 1=565-3623-ND, Tolerance_%=20%, Value1="0.012 ohm", Value2=20V, ValueDisplayed=680uF
C11: library part CMP-0008252-2, "CAP, CERM, 1500 pF, 250 V, +/- 10%, X7R, 0805", Cap_Case=0805, Manufacturer=MuRata, Supplier Part Number 1=490-3527-1-ND, TempCo=X7R, Tolerance_%=10%, Value1=Unknown, Value2=250V, ValueDisplayed=1500pF
C12: library part CMP-0008251-2, "CAP, CERM, 1000 pF, 250 V, +/- 10%, X7R, 0805", Cap_Case=0805, Manufacturer=MuRata, Supplier Part Number 1=490-3525-1-ND, TempCo=X7R, Tolerance_%=10%, Value1=Unknown, Value2=250V, ValueDisplayed=1000pF
C13 C19: library part CMP-0085817-1, "CAP, CERM, 22 µF, 35 V,+/- 20%, X5R, 1210", Cap_Case=1210, Manufacturer="Taiyo Yuden", TempCo=X5R, Tolerance_%=20%, Value2=35V, ValueDisplayed=22µF
C14 C15 C18: library part CMP-0008658-2, "CAP, CERM, 10 uF, 50 V, +/- 10%, X5R, 1206", Cap_Case=1206_180, Manufacturer=TDK, Supplier Part Number 1=445-5998-1-ND, TempCo=X5R, Tolerance_%=10%, Value1="0.002229 ohm", Value2=50V, ValueDisplayed=10uF
C16 C28 C29: library part CMP-0006348-2, "CAP, CERM, 22 pF, 50 V, +/- 5%, C0G/NP0, AEC-Q200 Grade 1, 0402", Cap_Case=0402, Manufacturer=MuRata, Supplier Part Number 1=490-9648-1-ND, TempCo=C0G/NP0, Tolerance_%=5%, Value1=Unknown, Value2=50V, ValueDisplayed=22pF
C17 C21: library part CMP-0006675-2, "CAP, CERM, 0.1 uF, 50 V, +/- 20%, X7R, 0402", Cap_Case=0402, Manufacturer=MuRata, Supplier Part Number 1=490-10701-1-ND, TempCo=X7R, Tolerance_%=20%, Value1=Unknown, Value2=50V, ValueDisplayed=0.1uF
C20: library part CMP-0081062-1, "CAP, CERM, 10 µF, 25 V,+/- 5%, X7R, AEC-Q200 Grade 1, 1206", Cap_Case=1206_180, Manufacturer=Kemet, Supplier Part Number 1=399-15734-1-ND, TempCo=X7R, Tolerance_%=5%, Value2=25V, ValueDisplayed=10µF
C22 C26: library part CMP-0006687-2, "CAP, CERM, 330 pF, 50 V, +/- 10%, X7R, 0402", Cap_Case=0402, Manufacturer=MuRata, Supplier Part Number 1=490-3247-1-ND, TempCo=X7R, Tolerance_%=10%, Value1=Unknown, Value2=50V, ValueDisplayed=330pF
C23: library part CMP-0007067-4, "CAP, CERM, 1 uF, 35 V, +/- 10%, X7R, AEC-Q200 Grade 1, 0603", Cap_Case=0603, Manufacturer=TDK, Supplier Part Number 1=445-174215-1-ND, TempCo=X7R, Tolerance_%=10%, Value1="0.005522 ohm", Value2=35V, ValueDisplayed=1uF
C24: library part CMP-0006679-2, "CAP, CERM, 0.015 uF, 50 V, +/- 10%, X7R, 0402", Cap_Case=0402, Manufacturer=MuRata, Supplier Part Number 1=490-4517-1-ND, TempCo=X7R, Tolerance_%=10%, Value1=Unknown, Value2=50V, ValueDisplayed=0.015uF
C25 C27: library part CMP-0006410-2, "CAP, CERM, 100 pF, 50 V, +/- 5%, C0G/NP0, 0402", Cap_Case=0402, Manufacturer=MuRata, Supplier Part Number 1=81-GRM1555C1H101JA1D, TempCo=C0G/NP0, Tolerance_%=5%, Value1=Unknown, Value2=50V, ValueDisplayed=100pF
C30: library part CMP-0006674-2, "CAP, CERM, 0.01 uF, 50 V, +/- 10%, X7R, 0402", Cap_Case=0402, Manufacturer=MuRata, Supplier Part Number 1=490-4516-1-ND, TempCo=X7R, Tolerance_%=10%, Value1=Unknown, Value2=50V, ValueDisplayed=0.01uF
C31: library part CMP-0006648-2, "CAP, CERM, 0.22 uF, 16 V, +/- 10%, X7R, 0402", Cap_Case=0402, Manufacturer=MuRata, Supplier Part Number 1=490-5418-1-ND, TempCo=X7R, Tolerance_%=10%, Value1=Unknown, Value2=16V, ValueDisplayed=0.22uF
D1: library part CMP-0084982-1, "Diode, TVS, Uni, 150 V, 243 Vc, 400 W, 1.6 A, SMA", Manufacturer=Littelfuse, Value1=243V
D2: library part CMP-0077082-2, "Diode, Standard Recovery Rectifier, 1000 V, 1 A, AEC-Q101, SMA", Manufacturer="ON Semiconductor", Value1=1A, Value2=1.1V
D3 D6: library part CMP-0029199-2, "Diode, Superfast Rectifier, 200 V, 1 A, 3.5x1.6mm", Manufacturer="Comchip Technology", Value1=1A, Value2=0.95V
D4: library part CMP-0084980-1, "Diode, TVS, Uni, 120 V, 193 Vc, 400 W, 2.1 A, SMA", Manufacturer=Littelfuse, Value1=193V
D5: library part CMP-0029006-2, "Diode, Ultrafast, 100 V, 0.25 A, SOD-323", Manufacturer=Nexperia, Value1=0.25A, Value2=1.4V
D7: library part CMP-0087587-1, "Diode, TVS, Bi, 18 V, SOD-323", Manufacturer="Bourns Inc."
D8: library part CMP-0028437-2, "Diode, Schottky, 40 V, 0.2 A, SOT-323", Manufacturer="Diodes Inc.", Value1=0.2A, Value2=0.8V
D9: library part CMP-0076957-3, "Diode, Switching, 75 V, 0.3 A, SOD-523", Manufacturer="Micro Commercial Components", Value1=0.3A, Value2=1.25V
D10: library part CMP-0005889-5, "Diode, Zener, 39 V, 350 mW, AEC-Q101, SOD-523", Manufacturer="Diodes Inc.", Power_W=350mW, Value1=0.35W
D11: library part CMP-0085774-1, "Diode, Zener, 27 V, 300 mW, AEC-Q101, SOD-323", Manufacturer="ON Semiconductor", Power_W=300mW, Value1=0.3W
DB1: "Diode, P-N-Bridge, 600 V, 4 A, Z4-D", Manufacturer="Comchip Technology", Supplier Part Number 1=641-1502-1-ND, Value1=4A, Value2=0.95V
F1: library part CMP-0003561-2, "Fuse, 3.15 A, 250VAC/VDC, TH", Irating_A=3.15A, Manufacturer=Littelfuse, Supplier Part Number 1=F5504CT-ND
J1 J2 J3: library part CMP-0074910-1, "Terminal Block, 5.08 mm, 2x1, Brass, TH", Color=Blue, Current_A=15A, Manufacturer="On-Shore Technology", Supplier Part Number 1=ED1609-ND, Voltage_V=300V
L1: library part CMP-0087546-1, "WE-FI Leaded Toroidal Line Choke", Manufacturer=Wurth
L2: library part CMP-0092946-1, "Common Mode Choke, 2.3mH 35%, 0.6x0.38x0.75 IN", Manufacturer=Renco, Operating Temperature Range=to, Test Frequency=10kHz, Tolerance_%=35%
Q1: library part CMP-0001046-2, "MOSFET, N-CH, 150 V, 87 A, PG-TDSON-8", Alternate Manufacturer=None, Manufacturer="Infineon Technologies", Supplier Part Number 1=BSC093N15NS5ATMA1CT-ND, Value2="33 nC"
Q2: library part CMP-0083711-2, "MOSFET, N-CH, 800 V, 8 A, DPAK", Alternate Manufacturer=None, Manufacturer="Infineon Technologies", Supplier Part Number 1=IPD80R600P7ATMA1CT-ND, Value1="? ohm", Value2="20 nC"
Q3: library part CMP-0081263-2, "MOSFET, N-CH, Depletion Mode, 800 V, SOT-23", Alternate Manufacturer=None, Manufacturer=IXYS, Supplier Part Number 1=CLA4160-1-ND, Value1="? ohm", Value2="? nC"
Q4: library part CMP-0077878-2, "Transistor, PNP, 40 V, 0.2 A, AEC-Q101, SOT-323", Manufacturer="Diodes Inc.", Value1="0.2 A", Value2=300.0
R1: library part CMP-0020554-3, "RES, 470 k, 5%, 0.125 W, AEC-Q200 Grade 0, 0805", Manufacturer=Vishay-Dale, Power_W=125mW, Supplier Part Number 1=541-470KACT-ND, TempCo="200 ppm/C", Tolerance_%=5%, Value2=0.125W, Value_Code=470k
R2 R3: library part CMP-0020464-3, "RES, 15, 5%, 0.125 W, AEC-Q200 Grade 0, 0805", Manufacturer=Vishay-Dale, Power_W=125mW, Supplier Part Number 1=541-15ACT-ND, TempCo="200 ppm/C", Tolerance_%=5%, Value2=0.125W, Value_Code=15R0, ValueDisplayed=15
R4: library part CMP-0018578-3, "RES, 10, 5%, 0.25 W, AEC-Q200 Grade 0, 1206", Manufacturer=Vishay-Dale, Power_W=250mW, Supplier Part Number 1=541-10ECT-ND, TempCo="200 ppm/C", Tolerance_%=5%, Value2=0.25W, Value_Code=10R0, ValueDisplayed=10
R5: library part CMP-0026827-3, "RES, 10, 5%, 0.063 W, AEC-Q200 Grade 0, 0402", Manufacturer=Vishay-Dale, Power_W=63mW, Supplier Part Number 1=541-10JCT-ND, TempCo="200 ppm/C", Tolerance_%=5%, Value2=0.063W, Value_Code=10R0, ValueDisplayed=10
R6: library part CMP-0089152-1, "100 Ohms ±1% 0.125W, 1/8W Chip Resistor 0603 (1608 Metric) Automotive AEC-Q200, Moisture Resistant Thick Film", Approved Alternate Part Number=541-1.00HHCT-ND, Digikey Part Number=2019-RK73H1JTTD1000FCT-ND, Manufacturer="KOA Speer", Mouser Part Number=660-RK73H1JTTD1000F, Operating Temperature Range="-55°C to +155°C", Power=100mW, TempCo=100ppm/°C, Tolerance_%=1%, Voltage=75V
R7 R20 R35: library part CMP-0025958-3, "RES, 10.0 k, 1%, 0.063 W, AEC-Q200 Grade 0, 0402", Manufacturer=Vishay-Dale, Power_W=63mW, Supplier Part Number 1=541-10.0KLCT-ND, TempCo="100 ppm/C", Tolerance_%=1%, Value2=0.063W, Value_Code=10k0, ValueDisplayed=10.0k
R8 R32: library part CMP-0026859-2, "RES, 1.0 M, 5%, 0.063 W, AEC-Q200 Grade 0, 0402", Manufacturer=Vishay-Dale, Power_W=63mW, Supplier Part Number 1=541-1.0MJCT-ND, TempCo="200 ppm/C", Tolerance_%=5%, Value2=0.063W, Value_Code=1M00, ValueDisplayed=1.0M
R9: library part CMP-0026721-1, "RES, 100 k, 1%, 0.0625 W, 0402", Manufacturer="Yageo America", Power_W=62.5mW, Supplier Part Number 1=311-100KLRCT-ND, TempCo="100 ppm/C", Tolerance_%=1%, Value2=0.0625W, Value_Code=100k
R10: library part CMP-0021844-3, "RES, 0.68, 1%, 0.125 W, AEC-Q200 Grade 0, 0805", Manufacturer=Panasonic, Power_W=125mW, Supplier Part Number 1=P.68DCT-ND, TempCo="250 ppm/C", Tolerance_%=1%, Value2=0.125W, Value_Code=R680, ValueDisplayed=0.68
R11: library part CMP-0015175-2, "RES, 0.22, 1%, 0.5 W, 1210", Manufacturer=Rohm, Power_W=500mW, Supplier Part Number 1=RHM.22SCT-ND, TempCo="200 ppm/C", Tolerance_%=1%, Value2=0.5W, Value_Code=R220, ValueDisplayed=0.22
R12 R28: library part CMP-0026436-2, "RES, 511, 1%, 0.063 W, AEC-Q200 Grade 0, 0402", Manufacturer=Vishay-Dale, Power_W=63mW, Supplier Part Number 1=541-511LCT-ND, TempCo="100 ppm/C", Tolerance_%=1%, Value2=0.063W, Value_Code=511R, ValueDisplayed=511
R13: library part CMP-0026298-2, "RES, 33.2 k, 1%, 0.063 W, AEC-Q200 Grade 0, 0402", Manufacturer=Vishay-Dale, Power_W=63mW, Supplier Part Number 1=541-33.2KLCT-ND, TempCo="100 ppm/C", Tolerance_%=1%, Value2=0.063W, Value_Code=33k2, ValueDisplayed=33.2k
R14 R17: library part CMP-0026229-2, "RES, 2.10 k, 1%, 0.063 W, AEC-Q200 Grade 0, 0402", Manufacturer=Vishay-Dale, Power_W=63mW, Supplier Part Number 1=541-2.10KLCT-ND, TempCo="100 ppm/C", Tolerance_%=1%, Value2=0.063W, Value_Code=2k10, ValueDisplayed=2.10k
R15: library part CMP-0026213-2, "RES, 27.4 k, 1%, 0.063 W, AEC-Q200 Grade 0, 0402", Manufacturer=Vishay-Dale, Power_W=63mW, Supplier Part Number 1=541-27.4KLCT-ND, TempCo="100 ppm/C", Tolerance_%=1%, Value2=0.063W, Value_Code=27k4, ValueDisplayed=27.4k
R16 R23: library part CMP-0026071-3, "RES, 1.00 k, 1%, 0.063 W, AEC-Q200 Grade 0, 0402", Manufacturer=Vishay-Dale, Power_W=63mW, Supplier Part Number 1=541-1.00KLCT-ND, TempCo="100 ppm/C", Tolerance_%=1%, Value2=0.063W, Value_Code=1k00, ValueDisplayed=1.00k
R18: library part CMP-0027004-2, "RES, 0, 5%, 0.063 W, 0402", Manufacturer="Yageo America", Power_W=63mW, Supplier Part Number 1=311-0.0JRCT-ND, TempCo="200 ppm/C", Tolerance_%=5%, Value2=0.063W, Value_Code=0000, ValueDisplayed=0
R19: library part CMP-0026028-3, "RES, 15.4 k, 1%, 0.063 W, AEC-Q200 Grade 0, 0402", Manufacturer=Vishay-Dale, Power_W=63mW, Supplier Part Number 1=541-15.4KLCT-ND, TempCo="100 ppm/C", Tolerance_%=1%, Value2=0.063W, Value_Code=15k4, ValueDisplayed=15.4k
R21: library part CMP-0026162-2, "RES, 20.0 k, 1%, 0.063 W, AEC-Q200 Grade 0, 0402", Manufacturer=Vishay-Dale, Power_W=63mW, Supplier Part Number 1=541-20.0KLCT-ND, TempCo="100 ppm/C", Tolerance_%=1%, Value2=0.063W, Value_Code=20k0, ValueDisplayed=20.0k
R22: library part CMP-0026518-2, "RES, 6.98 k, 1%, 0.063 W, AEC-Q200 Grade 0, 0402", Manufacturer=Vishay-Dale, Power_W=63mW, Supplier Part Number 1=541-6.98KLCT-ND, TempCo="100 ppm/C", Tolerance_%=1%, Value2=0.063W, Value_Code=6k98, ValueDisplayed=6.98k
R24: library part CMP-0026063-3, "RES, 191 k, 1%, 0.063 W, AEC-Q200 Grade 0, 0402", Manufacturer=Vishay-Dale, Power_W=63mW, Supplier Part Number 1=541-191KLCT-ND, TempCo="100 ppm/C", Tolerance_%=1%, Value2=0.063W, Value_Code=191k
R25: library part CMP-0026327-2, "RES, 39.2 k, 1%, 0.063 W, AEC-Q200 Grade 0, 0402", Manufacturer=Vishay-Dale, Power_W=63mW, Supplier Part Number 1=541-39.2KLCT-ND, TempCo="100 ppm/C", Tolerance_%=1%, Value2=0.063W, Value_Code=39k2, ValueDisplayed=39.2k
R26: library part CMP-0026027-3, "RES, 15.0 k, 1%, 0.063 W, AEC-Q200 Grade 0, 0402", Manufacturer=Vishay-Dale, Power_W=63mW, Supplier Part Number 1=541-15.0KLCT-ND, TempCo="100 ppm/C", Tolerance_%=1%, Value2=0.063W, Value_Code=15k0, ValueDisplayed=15.0k
R27: library part CMP-0026333-2, "RES, 3.32 k, 1%, 0.063 W, AEC-Q200 Grade 0, 0402", Manufacturer=Vishay-Dale, Power_W=63mW, Supplier Part Number 1=541-3.32KLCT-ND, TempCo="100 ppm/C", Tolerance_%=1%, Value2=0.063W, Value_Code=3k32, ValueDisplayed=3.32k
R29: library part CMP-0026038-3, "RES, 169 k, 1%, 0.063 W, AEC-Q200 Grade 0, 0402", Manufacturer=Vishay-Dale, Power_W=63mW, Supplier Part Number 1=541-169KLCT-ND, TempCo="100 ppm/C", Tolerance_%=1%, Value2=0.063W, Value_Code=169k
R30: library part CMP-0026023-3, "RES, 154 k, 1%, 0.063 W, AEC-Q200 Grade 0, 0402", Manufacturer=Vishay-Dale, Power_W=63mW, Supplier Part Number 1=541-154KLCT-ND, TempCo="100 ppm/C", Tolerance_%=1%, Value2=0.063W, Value_Code=154k
R31: library part CMP-0026609-3, "RES, 93.1 k, 1%, 0.063 W, AEC-Q200 Grade 0, 0402", Manufacturer=Vishay-Dale, Power_W=63mW, Supplier Part Number 1=541-93.1KLCT-ND, TempCo="100 ppm/C", Tolerance_%=1%, Value2=0.063W, Value_Code=93k1, ValueDisplayed=93.1k
R33: library part CMP-0026467-2, "RES, 5.62 k, 1%, 0.063 W, AEC-Q200 Grade 0, 0402", Manufacturer=Vishay-Dale, Power_W=63mW, Supplier Part Number 1=541-5.62KLCT-ND, TempCo="100 ppm/C", Tolerance_%=1%, Value2=0.063W, Value_Code=5k62, ValueDisplayed=5.62k
R34: library part CMP-0081856-1, "RES, 0, 0%, 0.2 W, AEC-Q200 Grade 0, 0402", Manufacturer=Vishay-Dale, Power_W=200mW, Supplier Part Number 1=541-0.0YBTR-ND, Tolerance_%=0%, Value2=0.2W, Value_Code=0
R36: library part CMP-0026367-2, "RES, 40.2 k, 1%, 0.063 W, AEC-Q200 Grade 0, 0402", Manufacturer=Vishay-Dale, Power_W=63mW, Supplier Part Number 1=541-40.2KLCT-ND, TempCo="100 ppm/C", Tolerance_%=1%, Value2=0.063W, Value_Code=40k2, ValueDisplayed=40.2k
R37 R38: library part CMP-0093609-1, "0Ω ±0 0.25W 1206 Thick Film Chip Resistor AEC-Q200 compliant", Manufacturer="Stackpole Electronics", Operating Temperature Range="-55°C to +155°C", Power_W=250mW
RT1: library part CMP-0002523-3, "Thermistor NTC, 47k ohm, 5%, 0603", Manufacturer=MuRata, Power_W=100mW, Supplier Part Number 1=490-2428-1-ND, Tolerance_%=5%
T1: library part CMP-0096030-1, "Transformer Flyback for PMP23195", Manufacturer="Renco Electronics", Operating Temperature Range=to, Voltage_Isolation_Vrms=3kV
TP1 TP3: library part CMP-0055149-1, "Test Point, Multipurpose, White, TH", Color=White, Manufacturer=Keystone, PartNumber=5012, Supplier Part Number 1=36-5012-ND
TP2: library part CMP-0055148-1, "Test Point, Multipurpose, Black, TH", Color=Black, Manufacturer=Keystone, PartNumber=5011, Supplier Part Number 1=36-5011-ND
U1: library part CMP-0089843-1, "Linear Voltage Regulator IC 1 Output 200mA SOT-23-5", Digikey Part Number=296-TPS7A2401DBVRCT-ND, Dropout Voltage=160mV, Manufacturer="Texas Instruments", Max Supply Voltage=18V, Min Supply Voltage=2.4V, Mouser Part Number=595-TPS7A2401DBVR, Nominal Supply Current=2uA, Operating Temperature Range="-40°C to +125°C", Output Voltage=1.24-17.75V
U2: library part CMP-0860377-2, "4-A/6-A, Single-Channel Reinforced Isolation Gate Driver with High Noise Immunity, DWV0008A (SOIC-8)", Alternate Manufacturer="Texas Instruments"
U3: library part CMP-0094229-1, "Zero-Voltage-Switching Flyback Controller with Dedicated Synchronous Rectifier Gate-Drive", Manufacturer="Texas Instruments", Max Supply Voltage=34V, Min Supply Voltage=14V, Nominal Supply Current=235-3000uA, Operating Temperature Range="-40°C to +125°C", Switching Frequency=1.5kHz
U4: library part CMP-0087394-2, "Optoisolator Transistor Output 5000Vrms 1 Channel 6-SO", Manufacturer=Toshiba
U5: library part CMP-0066199-1, "2.5V Low Iq Adjustable Precision Shunt Regulator, DBZ0003A (SOT-23-3)", Alternate Manufacturer="Texas Instruments"

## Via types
v1: diameter 27.56, hole 11.81, Top Layer to Bottom Layer, tented both sides, 30 vias
v2: diameter 27.56, hole 11.81, Top Layer to Bottom Layer, tented top, 20 vias
v3: diameter 19.68, hole 7.87, Top Layer to Bottom Layer, 5 vias
v4: diameter 24, hole 8, Top Layer to Bottom Layer, tented both sides, 4 vias
v5: diameter 27, hole 8, Top Layer to Bottom Layer, tented both sides, 4 vias
v6: diameter 27.56, hole 11.81, Top Layer to Bottom Layer, 4 vias

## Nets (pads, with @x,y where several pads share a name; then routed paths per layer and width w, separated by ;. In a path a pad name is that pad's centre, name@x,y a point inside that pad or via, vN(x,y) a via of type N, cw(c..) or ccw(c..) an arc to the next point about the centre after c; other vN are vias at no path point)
BUR: C26.1 R24.2 R25.1 U3.5 | length 341.5
  Signal Layer 1 w9.84: v1@1556.4,2311.9 v1(1559.42,2311.9) v1@1562.38,2314.85
  Signal Layer 1 w10: v1(1559.42,2311.9) 1572.52,2324 1728,2324 v1(1740,2334)
  Bottom Layer w7.87: U3.5@1538.49,2272.53 1538.49,2290.97 v1(1559.42,2311.9) 1557.1,2314.23 C26.1@1557.14,2349.3
  Bottom Layer w10: R24.2@1710,2305 1740,2305 v1(1740,2334)
CS: C25.1 Q4.3 R23.1 R32.2 U3.9 | length 907.2
  Signal Layer 2 w10: v1(1143,2370) 1170,2397 1582,2397 v1(1700,2278)
  Bottom Layer w8: U3.9@1583.77,2207.57 1601,2207.57 1614.11,2220.69 1635.37,2220.69 1654.29,2201.77 C25.1@1664.11,2201.77 ; 1700,2202 1737.59,2202 R23.1@1740,2204.41
  Bottom Layer w10: Q4.3@1112.61,2341 v1(1143,2370) ; C25.1@1664,2204 1666,2202 1700,2202 R32.2@1700,2230 v1(1700,2278)
FB: C22.2 R21.1 U3.6 | length 92.7
  Bottom Layer w7.87: U3.6@1558.18,2272.53 1594.9,2309.25 1594.9,2312.88 R21.1@1595,2350
FLT: C27.2 R27.2 U3.1 | length 98.2
  Bottom Layer w7.87: C27.2@1401.98,2311.9 1402.3,2311.58 C27.2@1404.27,2311.58 ; 1423.95,2291.9 1440.38,2291.9 U3.1@1459.75,2272.53
  Bottom Layer w8: R27.2@1375,2312 C27.2@1405.98,2312 ; C27.2@1415,2310.91 1423.95,2291.9
GND_C: C14.2 C15.2 J3.1 R13.1 T1.6 U1.2
  other v5: 949,2607.49 1055,2650.95 949,2690.02
GND_P: C1.2 C3.1 C4.1 C5.1 C7.2 C13.1 C16.1 C17.2 C18.2 C19.1 C21.2 C23.2 C25.2 C26.2 C27.1 C31.2 D11.1 DB1.4 R10.2 R11.1 R22.1 R25.2 R29.1 R31.1 R34.1 RT1.2 T1.4 U2.4 U3.8 U3.17 U3.18 U3.20 U3.21 U3.22 U3.25 U4.4 | length 2416.1
  Top Layer w10: 1055,1950 1190,2085 1355,2085 1365,2095 v1(1425,2095)
  Signal Layer 1 w30: v2(1230,2120) v2(1260,2120) v2(1260,1870)
  Bottom Layer w7.87: C31.2@1612.58,2243.67 C31.2@1624.99,2243.67
  Bottom Layer w8: 1596.16,2227.25 C31.2@1612.58,2243.67
  Bottom Layer w8.66: U3.21@1434.16,2187.49 U3.21@1434.16,2187.88
  Bottom Layer w10: D11.1@1158,2141 C19.1@1196.18,2141 ; R22.1@1380,2207 U3.25@1465,2207 ; 1405,2188 U3.25@1462.6,2188 ; C17.2@1413.2,2168.2 U3.25@1470,2168.2 ; v1(1425,2095) U3.18@1459.75,2122.92 U3.17@1479.44,2122.92 ; C26.2@1516.51,2348.67 C26.2@1517.14,2349.3 ; U3.25@1547.35,2227.25 1596.16,2227.25 ; C16.1@1583.77,1937 1583.77,1907.47 1596.24,1895 2056.07,1895 2063.14,1902.07 2063.14,1908.39 2075,1920.25 2075,1925 ; C31.2@1624.99,2243.67 1662.21,2243.67 C25.2@1664.11,2241.77 ; R34.1@1780,2267 R25.2@1780,2299 ; R34.1@1780,2270 v1(1809,2270) ; R11.1@2141.13,1975 2145.2,1970.93 v2(2145.2,1887.57) ; v2(2350,2140) U4.4@2350,2202.99
  Bottom Layer w20: C19.1@1280,2170 1405,2170 1405,2201.74 ; v1(1375,2348.67) C26.2@1516.51,2348.67 ; C23.2@1495,2050 v1(1525,2050)
  Bottom Layer w25: v2(1230,2120) C19.1@1230,2170 ; v2(1260,1870) C13.1@1300,1870 ; v2(1260,1905) C13.1@1312.35,1905 ; v2(1260,2120) C19.1@1260,2170
  other v2: 1936.75,992.02 2026.32,992.02 2070.71,992.02 1983.18,992.75 2105,1887.57 2190.68,1887.57 2230.63,1887.57
  other v3: 1508.96,2159.54 1470.78,2197.72 1508.96,2197.72 1547.15,2197.72 1508.96,2235.91
  other v4: 2470,1684.39 2510,1684.39 2553.1,1684.39 2598.51,1684.39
